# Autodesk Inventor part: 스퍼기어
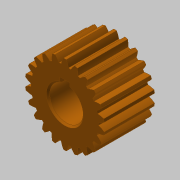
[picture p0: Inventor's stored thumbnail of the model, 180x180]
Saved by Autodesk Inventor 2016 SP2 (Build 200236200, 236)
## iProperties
Created: 2019-03
Part Number: 스퍼기어
Material: 강철
Document SubType Name: Modeling
Designer: mduedu
Categories: <?xml version="1.0" encoding="UTF-16"?> <MemberInstance><Categories><FamilyTemplate><FamilyTemplateParameter ValueType="xs:double" Id="1" ObjectReferenceKey="da
Density: 1 g/cm^3
Appearance: 주황색
CustomPartVersion: 1
Author: mduedu
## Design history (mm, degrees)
sketch "Sketch1"
  geometry: C1 r 23.6 at (0, 0)
  constraints: 1 centre point
  dimensions: "d0" = 47.2 diameter of C1 (= da_da)
extrude "Extrusion1" new body sketch "Sketch1" distance "d1" = 30 (= da_b); taper "d2" = 0 deg
workplane "Work Plane2"
sketch "Sketch2"
  geometry: C1 r 23.6 at (0, 0) reference; C2 r 22 at (0, 0)
  constraints: 1 centre point, 1 coincident
  dimensions: "d3" = 44 diameter of C2 (= da_dw)
feature "피치 지름" sketch "Sketch2" dims "d4" = 10, "d5" = 0
workplane "Work Plane8"
workplane "Work Plane9"
feature "스퍼 기어" dims "da_b" = 30, "da_d" = 44, "da_aw" = 44, "da_da" = 47.2, "da_df" = 40.172, "da_dw" = 44, angle "da_beta" = 0 deg, "da_lefttooth" = 0, "da_righttooth" = 0
sketch "스케치3"
  geometry: L1 (-3, 9.539)-(3, 9.539); L2 (3, 9.539)-(3, 12.8); L3 (3, 12.8)-(-3, 12.8); L4 (-3, 12.8)-(-3, 9.539); A1 r 10 centre (0, 0) between (-3, 9.539) and (3, 9.539); 1 further point
  constraints: 8 end point, 2 parallel, 2 point on circle, 1 centre point, 1 coincident, 1 horizontal, 1 perpendicular
  dimensions: "d49" = 20 diameter of A1; "d50" = 6 distance of L2.end L3.end; "d51" = 22.8 dimension on A1 L3
extrude "돌출2" cut sketch "스케치3" stored distance "d52" = 10; taper "d53" = 0 deg
chamfer "모따기1" distance "d54" = 1; stored, may be unused: second distance "d55" = 2, angle "d56" = 45 deg
body "Solid1"
body "Srf1"
other parameters: "d16" = 44 (= da_aw), "d17" = 0, "d34" = 1.428 (computed from da_z), "d39" = 0, "d41" = 0, "d43" = 44 (= da_aw), "d46" = 44 (= da_aw), "d47" = 0, "d48" = 0
